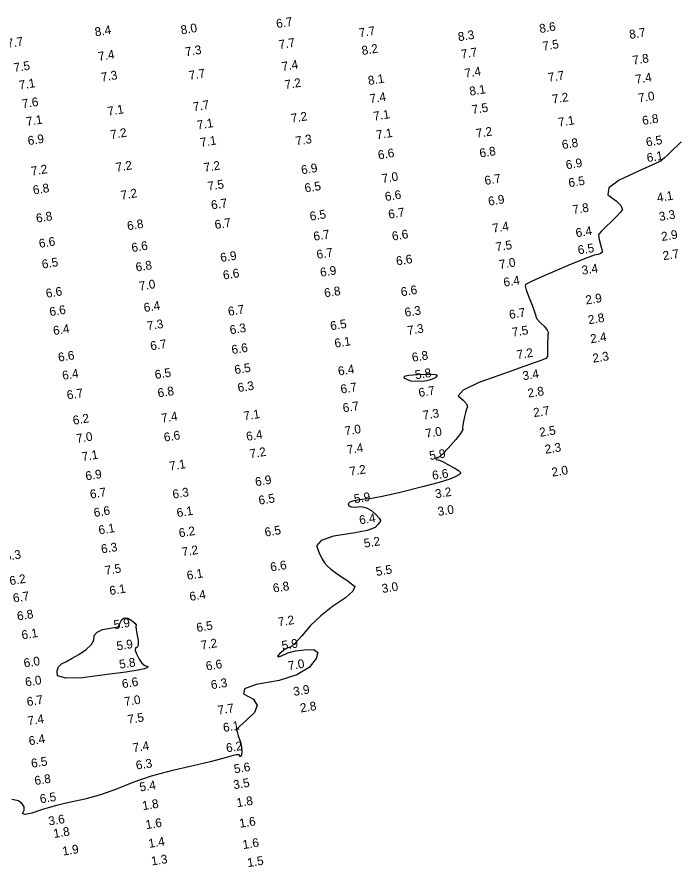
# Model space of a CAD drawing. Extents: x 988130 to 1132882, y 654656 to 841453.
# Drawn here: x 1107052.6 to 1107428, y 666087 to 666569.2 of the extents above; entities that cross this region are included whole.
import ezdxf

# ---------------------------------------------------------------- set-up
doc = ezdxf.new("R2010")
doc.units = 0
doc.layers.add('V-TOPO-MINR', color=7, linetype='Continuous')
doc.layers.add('V-TOPO-SOUN', color=7, linetype='Continuous')

msp = doc.modelspace()

# ---------------------------------------------------------------- linework, layer by layer
at = {"layer": 'V-TOPO-MINR'}
msp.add_lwpolyline([(1107429.33, 666498.32), (1107427.44, 666496.58), (1107424.95, 666494.24), (1107421.89, 666491.3), (1107419.76, 666489.27), (1107418.58, 666488.15), (1107418.34, 666487.94), (1107417.96, 666487.68), (1107417.46, 666487.36), (1107416.82, 666486.99), (1107412.7, 666485.09), (1107405.1, 666481.67), (1107394.02, 666476.73), (1107388.2, 666472.3), (1107387.65, 666468.4), (1107392.36, 666465.01), (1107395.12, 666462.22), (1107395.93, 666460.03), (1107394.79, 666458.44), (1107392.82, 666456.23), (1107390.03, 666453.41), (1107386.4, 666449.97), (1107383.92, 666447.5), (1107382.59, 666446.01), (1107382.39, 666445.5), (1107382.52, 666444.22), (1107382.98, 666442.2), (1107383.75, 666439.42), (1107384.25, 666437.39), (1107384.45, 666436.1), (1107384.38, 666435.56), (1107383.6, 666435.04), (1107382.13, 666434.52), (1107379.96, 666434.01), (1107374.43, 666431.96), (1107365.55, 666428.36), (1107353.3, 666423.2), (1107345.08, 666419.54), (1107340.9, 666417.37), (1107340.76, 666416.68), (1107341.35, 666414.5), (1107342.67, 666410.83), (1107344.73, 666405.66), (1107346.11, 666401.98), (1107346.81, 666399.78), (1107346.83, 666399.06), (1107347.66, 666397.79), (1107349.3, 666395.95), (1107351.75, 666393.56), (1107353.3, 666391.58), (1107353.96, 666390.01), (1107353.71, 666388.86), (1107353.55, 666387.06), (1107353.46, 666384.61), (1107353.46, 666381.51), (1107353.47, 666379.12), (1107353.48, 666377.46), (1107353.5, 666376.53), (1107352.44, 666375.53), (1107350.29, 666374.47), (1107347.06, 666373.35), (1107340.01, 666370.87), (1107329.15, 666367.04), (1107314.48, 666361.86), (1107305.67, 666357.59), (1107302.74, 666354.23), (1107305.68, 666351.77), (1107307.45, 666349.71), (1107308.06, 666348.03), (1107307.5, 666346.73), (1107306.93, 666344.93), (1107306.35, 666342.62), (1107305.75, 666339.8), (1107305.4, 666337.62), (1107305.3, 666336.07), (1107305.44, 666335.15), (1107304.14, 666332.95), (1107301.39, 666329.46), (1107297.2, 666324.68), (1107294.11, 666321.4), (1107292.11, 666319.63), (1107291.21, 666319.35), (1107290.57, 666319.07), (1107290.19, 666318.79), (1107290.08, 666318.51), (1107290.38, 666318.24), (1107291.1, 666317.97), (1107292.24, 666317.71), (1107294.19, 666316.86), (1107296.95, 666315.41), (1107300.51, 666313.38), (1107302.88, 666311.85), (1107304.07, 666310.83), (1107304.06, 666310.3), (1107303.07, 666309.51), (1107301.09, 666308.44), (1107298.13, 666307.09), (1107291.92, 666305.15), (1107282.49, 666302.62), (1107269.81, 666299.5), (1107260.6, 666297.34), (1107254.84, 666296.15), (1107252.54, 666295.93), (1107249.89, 666295.61), (1107246.89, 666295.21), (1107243.54, 666294.71), (1107241.39, 666294.01), (1107240.46, 666293.09), (1107240.73, 666291.97), (1107242.03, 666291.32), (1107244.37, 666291.16), (1107247.73, 666291.47), (1107250.83, 666290.83), (1107253.67, 666289.25), (1107256.25, 666286.72), (1107257.95, 666284.89), (1107258.77, 666283.76), (1107258.72, 666283.33), (1107258.21, 666282.49), (1107257.22, 666281.24), (1107255.76, 666279.59), (1107251.08, 666277.94), (1107243.17, 666276.31), (1107232.03, 666274.69), (1107225.1, 666272.3), (1107222.38, 666269.15), (1107223.87, 666265.24), (1107225.37, 666262.06), (1107226.89, 666259.63), (1107228.42, 666257.93), (1107230.56, 666256.05), (1107233.31, 666253.97), (1107236.67, 666251.69), (1107239.61, 666249.64), (1107242.12, 666247.81), (1107244.22, 666246.19), (1107243.13, 666243.48), (1107238.86, 666239.66), (1107231.41, 666234.73), (1107224.81, 666229.51), (1107219.07, 666223.97), (1107214.17, 666218.14), (1107210.5, 666214.12), (1107208.06, 666211.93), (1107206.84, 666211.56), (1107205.74, 666211.11), (1107204.75, 666210.59), (1107203.87, 666210), (1107202.83, 666209.15), (1107201.64, 666208.05), (1107200.29, 666206.68), (1107200.6, 666206.3), (1107202.57, 666206.89), (1107206.2, 666208.45), (1107210.46, 666209.55), (1107215.36, 666210.19), (1107220.89, 666210.35), (1107223.22, 666208.74), (1107222.33, 666205.35), (1107218.24, 666200.18), (1107211.19, 666196), (1107201.19, 666192.79), (1107188.24, 666190.57), (1107181.5, 666188.07), (1107180.95, 666185.29), (1107186.62, 666182.23), (1107188.74, 666178.67), (1107187.32, 666174.59), (1107182.35, 666170.01), (1107178.99, 666166.89), (1107177.23, 666165.23), (1107177.06, 666165.03), (1107177.35, 666163.74), (1107178.08, 666161.36), (1107179.27, 666157.88), (1107179.96, 666154.95), (1107180.14, 666152.56), (1107179.82, 666150.7), (1107179.46, 666149.75), (1107179.07, 666149.7), (1107178.64, 666150.55), (1107176.87, 666150.64), (1107173.75, 666149.97), (1107169.3, 666148.54), (1107162.18, 666146.66), (1107152.39, 666144.34), (1107139.94, 666141.56), (1107128.56, 666138.44), (1107118.25, 666134.98), (1107109.03, 666131.17), (1107099.92, 666128.01), (1107090.94, 666125.49), (1107082.09, 666123.61), (1107074.14, 666121.66), (1107067.11, 666119.63), (1107060.98, 666117.52), (1107057.19, 666116.76), (1107055.75, 666117.37), (1107056.63, 666119.33), (1107056.55, 666121.18), (1107055.49, 666122.9), (1107053.45, 666124.51), (1107049.55, 666125.32)], dxfattribs=at)
for points in [[(1107275.72, 666362.86), (1107282.23, 666362.64), (1107285.2, 666362.98), (1107287.91, 666363.75), (1107290.34, 666364.97), (1107291.07, 666365.82), (1107290.09, 666366.3), (1107287.4, 666366.42), (1107283.97, 666366.37), (1107279.8, 666366.15), (1107274.88, 666365.77), (1107272.24, 666365.23), (1107271.88, 666364.54)], [(1107109.89, 666223.27), (1107112.01, 666227.5), (1107113.53, 666228.42), (1107115.48, 666228.14), (1107117.89, 666226.66), (1107119.44, 666225.39), (1107120.13, 666224.35), (1107119.97, 666223.52), (1107120.11, 666221.81), (1107120.53, 666219.22), (1107121.23, 666215.74), (1107121.35, 666213.27), (1107120.88, 666211.8), (1107119.82, 666211.33), (1107119.62, 666210.02), (1107120.27, 666207.86), (1107121.77, 666204.85), (1107123.34, 666202.66), (1107124.98, 666201.3), (1107126.67, 666200.76), (1107126.61, 666200.15), (1107124.8, 666199.47), (1107121.23, 666198.71), (1107114.19, 666197.61), (1107103.68, 666196.17), (1107089.7, 666194.38), (1107080.3, 666194.13), (1107075.49, 666195.41), (1107075.26, 666198.23), (1107076.04, 666200.53), (1107077.85, 666202.33), (1107080.67, 666203.62), (1107083.93, 666205.39), (1107087.65, 666207.64), (1107091.81, 666210.36), (1107094.65, 666213.05), (1107096.16, 666215.7), (1107096.35, 666218.31), (1107097.95, 666220.31), (1107100.98, 666221.7)]]:
    msp.add_lwpolyline(points, close=True, dxfattribs=at)

# ---------------------------------------------------------------- texts
at = {"layer": 'V-TOPO-SOUN'}
for s, p in [('8.0', (1107145.81, 666559.33)), ('6.7', (1107199.96, 666562.88)), ('8.6', (1107349.19, 666560.09)), ('8.4', (1107097.06, 666558.21)), ('7.7', (1107246.85, 666557.68)), ('8.3', (1107303.04, 666555.47)), ('8.7', (1107400.23, 666556.79)), ('7.7', (1107047.26, 666551.63)), ('7.7', (1107201.4, 666551)), ('7.5', (1107351.01, 666550.13)), ('7.3', (1107148.31, 666546.91)), ('8.2', (1107248.43, 666547.63)), ('7.7', (1107304.78, 666545.57)), ('7.4', (1107098.97, 666544.3)), ('7.8', (1107402.04, 666542.12)), ('7.5', (1107051.05, 666537.94)), ('7.4', (1107203.12, 666538.59)), ('7.3', (1107100.59, 666532.52)), ('7.7', (1107150.4, 666533.53)), ('8.1', (1107252.01, 666530.6)), ('7.4', (1107306.83, 666534.74)), ('7.7', (1107354.1, 666532.39)), ('7.4', (1107403.68, 666531.34)), ('7.1', (1107054.05, 666528.03)), ('7.2', (1107204.77, 666528.26)), ('8.1', (1107309.54, 666524.54)), ('7.0', (1107405.3, 666520.74)), ('7.6', (1107055.79, 666517.38)), ('7.7', (1107152.75, 666515.72)), ('7.4', (1107252.97, 666520.29)), ('7.2', (1107356.47, 666520.08)), ('7.1', (1107104.27, 666513.19)), ('7.5', (1107310.91, 666514.13)), ('7.1', (1107058.13, 666507.34)), ('7.2', (1107208.31, 666509.22)), ('7.1', (1107255.07, 666510.37)), ('7.1', (1107359.89, 666506.95)), ('6.8', (1107407.54, 666507.91)), ('7.1', (1107155.07, 666505.38)), ('6.9', (1107059.01, 666496.5)), ('7.2', (1107105.92, 666499.93)), ('7.1', (1107256.66, 666499.79)), ('7.2', (1107313.25, 666500.64)), ('7.1', (1107156.83, 666495.51)), ('7.3', (1107210.91, 666496.32)), ('6.8', (1107361.97, 666494.23)), ('6.5', (1107409.69, 666495.72)), ('6.6', (1107257.67, 666488.4)), ('6.8', (1107315.25, 666489.46)), ('6.9', (1107364.25, 666482.79)), ('6.1', (1107410.13, 666486.83)), ('7.2', (1107060.93, 666479.22)), ('7.2', (1107108.96, 666481.42)), ('7.2', (1107158.9, 666481.31)), ('6.9', (1107214.12, 666479.92)), ('7.0', (1107259.87, 666475.02)), ('6.7', (1107318.12, 666473.9)), ('6.5', (1107365.75, 666472.63)), ('6.8', (1107061.97, 666468.52)), ('7.5', (1107161.05, 666470.66)), ('6.5', (1107216.06, 666469.64)), ('7.2', (1107111.79, 666465.57)), ('6.6', (1107261.62, 666464.75)), ('4.1', (1107415.9, 666464.22)), ('6.7', (1107163.02, 666460)), ('6.9', (1107320.19, 666462.13)), ('6.5', (1107218.95, 666453.62)), ('6.7', (1107263.54, 666454.74)), ('7.8', (1107368.03, 666457.38)), ('3.3', (1107417.06, 666453.46)), ('6.8', (1107063.72, 666452.54)), ('6.7', (1107165.04, 666448.87)), ('6.8', (1107115.39, 666448.2)), ('7.4', (1107322.63, 666446.82)), ('6.4', (1107369.8, 666444.23)), ('6.7', (1107221.04, 666442.24)), ('6.6', (1107265.61, 666442.35)), ('2.9', (1107418.38, 666442.12)), ('6.6', (1107065.37, 666438.2)), ('6.6', (1107117.86, 666435.81)), ('7.5', (1107324.46, 666436.23)), ('6.5', (1107371.03, 666434.48)), ('6.9', (1107168.24, 666430.19)), ('6.7', (1107222.86, 666431.95)), ('2.7', (1107419.23, 666431.23)), ('6.5', (1107067.05, 666426.44)), ('6.8', (1107120.23, 666424.76)), ('6.6', (1107267.95, 666428.23)), ('7.0', (1107326.42, 666426.28)), ('6.6', (1107169.76, 666420.23)), ('6.9', (1107224.85, 666421.79)), ('3.4', (1107373.23, 666422.95)), ('6.4', (1107328.85, 666416.15)), ('6.6', (1107069.32, 666409.89)), ('7.0', (1107122.18, 666414)), ('6.8', (1107227.18, 666410.13)), ('6.6', (1107270.67, 666410.74)), ('2.9', (1107375.41, 666406.11)), ('6.4', (1107124.83, 666401.82)), ('6.6', (1107071.35, 666399.46)), ('6.7', (1107172.6, 666399.66)), ('6.3', (1107272.79, 666399.09)), ('6.7', (1107332.06, 666397.9)), ('7.3', (1107126.67, 666391.43)), ('6.5', (1107230.63, 666391.45)), ('2.8', (1107376.84, 666394.89)), ('6.4', (1107073.44, 666388.74)), ('6.3', (1107173.57, 666389.16)), ('7.3', (1107274.31, 666388.81)), ('7.5', (1107333.67, 666387.84)), ('6.1', (1107233, 666381.61)), ('2.4', (1107378.08, 666384.08)), ('6.7', (1107128.55, 666380.06)), ('6.6', (1107174.62, 666377.92)), ('6.6', (1107076.25, 666373.61)), ('6.8', (1107276.91, 666373.58)), ('7.2', (1107336.37, 666375.08)), ('2.3', (1107379.39, 666373.09)), ('6.5', (1107176.25, 666366.57)), ('6.4', (1107078.61, 666363.33)), ('6.5', (1107131.07, 666363.78)), ('6.4', (1107235, 666365.76)), ('5.8', (1107278.67, 666363.64)), ('3.4', (1107339.69, 666363.11)), ('6.7', (1107081.2, 666352.2)), ('6.8', (1107132.7, 666353.38)), ('6.3', (1107178.07, 666356.39)), ('6.7', (1107236.46, 666355.56)), ('6.7', (1107280.69, 666353.62)), ('2.8', (1107342.57, 666353.27)), ('6.7', (1107237.67, 666344.9)), ('2.7', (1107345.78, 666342.2)), ('6.2', (1107084.6, 666337.87)), ('7.4', (1107134.76, 666339.08)), ('7.1', (1107181.44, 666340.31)), ('7.3', (1107283.07, 666340.74)), ('6.6', (1107136.25, 666328.25)), ('6.4', (1107182.97, 666328.74)), ('7.0', (1107238.77, 666331.8)), ('7.0', (1107284.62, 666330.43)), ('2.5', (1107349.22, 666331.03)), ('7.0', (1107086.54, 666327.52)), ('7.2', (1107184.9, 666318.86)), ('7.4', (1107240.07, 666321.2)), ('2.3', (1107352.3, 666321.43)), ('7.1', (1107089.72, 666317.25)), ('5.9', (1107286.79, 666317.86)), ('7.1', (1107139.36, 666311.92)), ('7.2', (1107241.55, 666308.9)), ('2.0', (1107356.2, 666308.44)), ('6.9', (1107091.75, 666306.27)), ('6.6', (1107288.37, 666306.62)), ('6.9', (1107188.02, 666302.99)), ('6.7', (1107094.32, 666295.95)), ('6.3', (1107141.15, 666295.94)), ('3.2', (1107290.13, 666296.15)), ('6.5', (1107189.95, 666292.5)), ('5.9', (1107244.07, 666293.37)), ('6.6', (1107096.45, 666285.5)), ('6.1', (1107143.5, 666285.42)), ('3.0', (1107291.51, 666286.12)), ('6.4', (1107247.04, 666281.32)), ('6.1', (1107099.2, 666275.61)), ('6.2', (1107144.72, 666273.99)), ('6.5', (1107193.39, 666274.42)), ('5.2', (1107249.7, 666268.12)), ('6.3', (1107045.93, 666260.59)), ('6.3', (1107100.61, 666264.86)), ('7.2', (1107146.44, 666263.18)), ('7.5', (1107102.76, 666252.7)), ('6.6', (1107196.6, 666254.63)), ('5.5', (1107256.44, 666252.09)), ('6.2', (1107048.66, 666246.84)), ('6.1', (1107149.23, 666249.88)), ('6.1', (1107105.33, 666241.23)), ('6.8', (1107198.09, 666242.67)), ('3.0', (1107259.87, 666242.39)), ('6.7', (1107050.65, 666237.04)), ('6.4', (1107150.76, 666237.94)), ('6.8', (1107052.94, 666226.83)), ('5.9', (1107107.77, 666221.87)), ('7.2', (1107200.93, 666223.46)), ('6.5', (1107154.71, 666220.32)), ('6.1', (1107055.53, 666216.1)), ('5.9', (1107109.42, 666209.83)), ('7.2', (1107157.23, 666210.29)), ('5.9', (1107203.07, 666210.16)), ('6.0', (1107056.71, 666200.17)), ('5.8', (1107110.9, 666199.42)), ('6.6', (1107160.07, 666198.47)), ('7.0', (1107206.69, 666198.65)), ('6.0', (1107057.59, 666189.38)), ('6.6', (1107112.46, 666188.4)), ('6.3', (1107162.93, 666187.82)), ('3.9', (1107209.63, 666184.04)), ('6.7', (1107058.48, 666178.23)), ('7.0', (1107113.78, 666178.26)), ('7.7', (1107166.78, 666173.43)), ('2.8', (1107213.5, 666174.65)), ('7.4', (1107058.96, 666167.33)), ('7.5', (1107115.68, 666168.19)), ('6.1', (1107169.8, 666163.59)), ('6.4', (1107059.58, 666156.02)), ('7.4', (1107118.61, 666152.12)), ('6.2', (1107171.51, 666152.01)), ('6.5', (1107060.93, 666143.26)), ('6.3', (1107120.37, 666142.17)), ('5.6', (1107176, 666140.08)), ('6.8', (1107062.86, 666133.43)), ('3.5', (1107175.61, 666131.09)), ('5.4', (1107122.43, 666129.79)), ('6.5', (1107065.9, 666123.11)), ('1.8', (1107177.46, 666120.89)), ('1.8', (1107124.01, 666119.24)), ('3.6', (1107070.76, 666110.52)), ('1.6', (1107125.86, 666108.43)), ('1.6', (1107179.05, 666109.23)), ('1.8', (1107073.58, 666103.44)), ('1.4', (1107127.49, 666097.82)), ('1.6', (1107180.9, 666097.14)), ('1.9', (1107078.7, 666093.44)), ('1.3', (1107129.04, 666087.8)), ('1.5', (1107183.54, 666086.92))]:
    msp.add_text(s, height=5, rotation=9.0039, dxfattribs=at).set_placement(p)

doc.saveas('drawing.dxf')
